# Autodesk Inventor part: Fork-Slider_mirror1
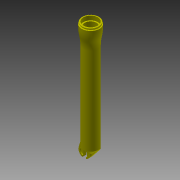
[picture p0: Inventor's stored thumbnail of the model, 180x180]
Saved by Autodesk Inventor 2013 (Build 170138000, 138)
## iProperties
Shininess: 64.0
Length Units: 11272
Angle Units: 11279
Time Units: 11290
Mass Units: 11286
Length Display Precision: 3
Angle Display Precision: 2
Compacted: True
Part Number: Fork-Slider_mirror1
Document SubType Name: Modeling
Created: 2003-10
Designer: Autodesk, Inc.
Material: Generic
Manufacturer: Standard
Standards Organization: Custom
Mass: 115.052 g
Surface Area: 625.893 cm^2
Volume: 115.052 cm^3
Density: 1 g/cm^3
Density: 0.0
Volumn: 0.0
Area: 0.0
PropertySet Name: Model Information
Control State: 0
Master: False
Checked Out: False
Author: Autodesk, Inc.
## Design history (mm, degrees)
derived "Fork-Slider.ipt"
  workplane "Work Plane3"
  node "WorkPlane4"
  workplane "Work Plane8"
  node "WorkPlane5"
  node "WorkPlane1"
  node "WorkPlane2"
  node "WorkPlane3"
  node "WorkAxis1"
body "Solid1"
tag "TaggingFeature2"
workplane "Work Plane10"
workplane "Work Plane11"
workplane "Work Plane5"
workplane "Work Plane6"
feature "DerivedBody::Fork-Slider.ipt"
